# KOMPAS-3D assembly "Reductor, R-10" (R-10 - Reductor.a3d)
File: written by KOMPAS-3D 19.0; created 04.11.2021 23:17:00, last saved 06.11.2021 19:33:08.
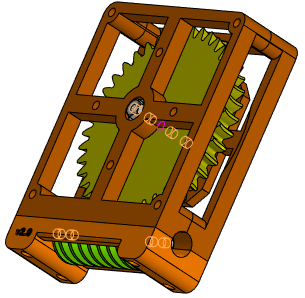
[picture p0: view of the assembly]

Document properties: Полное имя файла: D:\3D_print\3D проекты Компас 3D\Редуктор (Снова)\R-10 - Reductor.a3d

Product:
- Part/product: Reductor  | designation R-10
    Материал: АБС 0603Т ТУ 2214-019-002 03521-96 (density 0 kg/m3)
    Масса: 0.009492
  - Component [detail]: Korpus(3)  | Материал: АБС 0603Т ТУ 2214-019-002 03521-96 (density 0 kg/m3); source file: Korpus(3).m3d
  - Component [detail]: Korpus(2)  | Материал: АБС 0603Т ТУ 2214-019-002 03521-96 (density 0 kg/m3); source file: Korpus(2).m3d
  - Component [detail]: ChervKoleso  | Материал: АБС 0603Т ТУ 2214-019-002 03521-96 (density 0 kg/m3); Комментарий: Модуль генерации 3D-моделей программы "Валы и механические передачи 2D"; source file: ChervKoleso.m3d
  - Component [detail]: Chervyak  | Материал: АБС 0603Т ТУ 2214-019-002 03521-96 (density 0 kg/m3); source file: Chervyak.m3d
  - Component [standard]: Шайба A.3.37 ГОСТ 11371-78  | qty 3  | Материал: АД1 ГОСТ 4784-97 (density 1000 kg/m3); Масса: 0.000119; Раздел спецификации: Стандартные изделия; Рассекать на разрезах: no; source file: C:\Program Files\ASCON\KOMPAS-3D v19\Libs\PARTLib\DATA\vault\Methods\Kompas\3D\PLib_Washer_1_712.m3d
  - Component [standard]: Гайка М3-6H ГОСТ 5915-70  | qty 8  | Масса: 0.000377; Раздел спецификации: Стандартные изделия; Рассекать на разрезах: no; source file: C:\Program Files\ASCON\KOMPAS-3D v19\Libs\PARTLib\DATA\vault\Methods\Kompas\3D\PLib_Nut_OST92_900.m3d
  - Component [standard]: Подшипник 23 ГОСТ 8338-75  | qty 4  | Масса: 0.0015; Раздел спецификации: Стандартные изделия; Рассекать на разрезах: no; additional columns: 23; source file: C:\Program Files\ASCON\KOMPAS-3D v19\Libs\PARTLib\DATA\vault\Methods\Kompas\3D\Bearings\8338_75\PLib_Bearing_GOST_8338_75_712.a3d
  - Component [detail]: Korpus(1)  | Материал: АБС 0603Т ТУ 2214-019-002 03521-96 (density 0 kg/m3); source file: Korpus(1_v2).m3d

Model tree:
1. Эскиз:1  (with: Элемент выдавливания:4, Элемент выдавливания:2, Элемент выдавливания:3, Элемент выдавливания:9, Элемент выдавливания:1)  (labels: Фаска:3; Фаска:3; Фаска:3; Фаска:3)
     Ориентация = 2; Ориентация = 2; Ориентация = 2; Ориентация = 2

Referenced files in D:\3D_print\3D проекты Компас 3D\Редуктор (Снова)\: ChervKoleso.m3d, Chervyak.m3d, Korpus(1_v2).m3d, Korpus(2).m3d, Korpus(3).m3d
Referenced files: SPDS_GR_2014.LYT, SPDS.tdp
Referenced files in C:\Program Files\ASCON\KOMPAS-3D v19\Libs\PARTLib\DATA\vault\Methods\Kompas\3D\: PLib_Washer_1_712.m3d, PLib_Nut_OST92_900.m3d
Referenced files in C:\Program Files\ASCON\KOMPAS-3D v19\Libs\PARTLib\DATA\vault\Methods\Kompas\3D\Bearings\8338_75\: PLib_Bearing_GOST_8338_75_712.a3d
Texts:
  01 Спецификация. ГОСТ Р 21.1101-2013 Ф7
  bcut1
  hole1
  hcut1
  hole2
  cut1
  Внеш. контур, ступень 1: Червячное колесо (тип ZA, правое) Z=40, L=6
